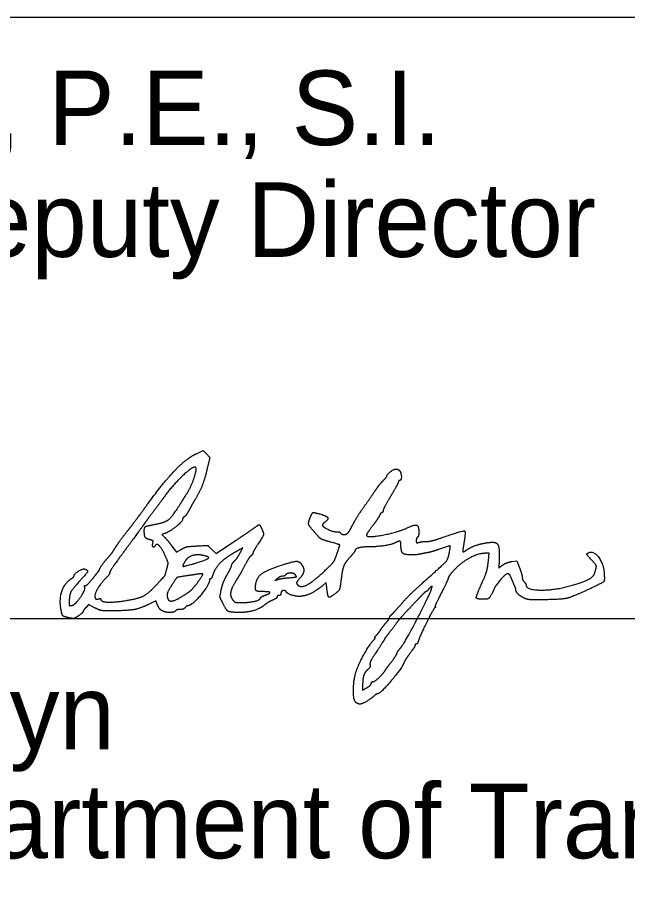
# Model space of a CAD drawing. Extents: x 0 to 39.4, y 0 to 22.
# Drawn here: x 25.677 to 26.824, y 7.305 to 8.926 of the extents above; entities that cross this region are included whole.
import ezdxf

# ---------------------------------------------------------------- set-up
doc = ezdxf.new("R2010")
doc.units = 0
for name, color, linetype in [('PV_P_Bikeway', 7, 'Continuous'), ('SH_Data', 7, 'Continuous'), ('SH_Text', 7, 'Continuous')]:
    doc.layers.add(name, color=color, linetype=linetype)

msp = doc.modelspace()

# ---------------------------------------------------------------- linework, layer by layer
at = {"layer": 'PV_P_Bikeway'}
for points in [[(26.0135, 8.1066), (26.0261, 8.1124), (26.0325, 8.1061), (26.0388, 8.0997), (26.0344, 8.081)], [(25.9536, 7.9566), (25.9486, 7.955), (25.9537, 7.9499)], [(25.9674, 7.9332), (25.9759, 7.9217), (25.9847, 7.9269)], [(26.0425, 7.9269), (26.0507, 7.9193), (26.0869, 7.9434)], [(26.0964, 7.9216), (26.1009, 7.9296), (26.0954, 7.9266)], [(26.5623, 7.9057), (26.5638, 7.9195), (26.5559, 7.9195)], [(26.6061, 7.9041), (26.6158, 7.9056), (26.6209, 7.8921)], [(26.2582, 7.8579), (26.2575, 7.8648), (26.2516, 7.8596)], [(25.8219, 7.8173), (25.8104, 7.8231), (25.8054, 7.8173)], [(25.9406, 7.8223), (25.9372, 7.8304), (25.9234, 7.8235)], [(26.3259, 7.6718), (26.3259, 7.6624), (26.3335, 7.6668)]]:
    msp.add_lwpolyline(points, dxfattribs=at)
for points in [[(25.9239, 8.0147), (25.9536, 8.0553), (25.9954, 8.0982), (26.0135, 8.1066)], [(26.012, 8.0808), (26.0084, 8.0844), (25.9698, 8.0487), (25.9545, 8.0274)], [(25.9937, 8.0287), (26.0032, 8.0436), (26.0151, 8.0777), (26.012, 8.0808)], [(26.0344, 8.081), (26.0294, 8.0598), (26.0203, 8.0362), (26.0108, 8.0203)], [(26.3715, 8.0646), (26.3715, 8.0675), (26.3847, 8.0778), (26.3884, 8.0778)], [(26.3884, 8.0778), (26.3905, 8.0779), (26.3935, 8.0766), (26.395, 8.075)], [(26.3649, 8.0565), (26.3686, 8.0602), (26.3715, 8.0638), (26.3715, 8.0646)], [(26.395, 8.075), (26.3985, 8.0716), (26.3989, 8.0563), (26.3955, 8.0563)], [(26.3511, 8.0393), (26.3551, 8.0452), (26.3613, 8.0529), (26.3649, 8.0565)], [(26.3931, 8.0538), (26.3931, 8.0524), (26.3866, 8.0403), (26.3787, 8.0269)], [(26.3955, 8.0563), (26.3942, 8.0563), (26.3931, 8.0552), (26.3931, 8.0538)], [(25.9545, 8.0274), (25.9509, 8.0224), (25.9414, 8.0098), (25.9335, 7.9993)], [(25.9832, 8.012), (25.9865, 8.0172), (25.9912, 8.0248), (25.9937, 8.0287)], [(26.3295, 8.0083), (26.3375, 8.0195), (26.3472, 8.0335), (26.3511, 8.0393)], [(25.8838, 7.9612), (25.8927, 7.9726), (25.9107, 7.9966), (25.9239, 8.0147)], [(25.9334, 7.9734), (25.954, 7.9771), (25.9681, 7.988), (25.9832, 8.012)], [(26.0108, 8.0203), (26.0073, 8.0144), (26.0021, 8.0052), (25.9993, 7.9999)], [(26.3787, 8.0269), (26.3708, 8.0135), (26.3643, 8.0012), (26.3643, 7.9994)], [(25.9335, 7.9993), (25.9256, 7.9888), (25.9175, 7.9778), (25.9155, 7.9748)], [(25.9993, 7.9999), (25.9964, 7.9946), (25.9926, 7.9894), (25.9908, 7.9884)], [(26.2275, 7.9866), (26.2312, 7.9956), (26.2343, 7.9966), (26.2471, 7.9929)], [(26.3081, 7.9747), (26.312, 7.982), (26.3216, 7.9971), (26.3295, 8.0083)], [(26.3623, 7.9963), (26.3612, 7.9963), (26.3589, 7.9933), (26.3571, 7.9897)], [(26.3643, 7.9994), (26.3643, 7.9977), (26.3634, 7.9963), (26.3623, 7.9963)], [(25.9875, 7.983), (25.9875, 7.9792), (25.9618, 7.9592), (25.9536, 7.9566)], [(25.9908, 7.9884), (25.989, 7.9873), (25.9875, 7.9849), (25.9875, 7.983)], [(26.2373, 7.9571), (26.2257, 7.9702), (26.2235, 7.977), (26.2275, 7.9866)], [(26.2471, 7.9929), (26.259, 7.9893), (26.2619, 7.9831), (26.2542, 7.9773)], [(26.3571, 7.9897), (26.3553, 7.9861), (26.3492, 7.977), (26.3435, 7.9695)], [(25.9155, 7.9748), (25.9135, 7.9719), (25.8982, 7.9509), (25.8814, 7.9283)], [(25.9155, 7.9613), (25.9155, 7.9681), (25.9196, 7.9709), (25.9334, 7.9734)], [(26.0869, 7.9434), (26.1068, 7.9566), (26.1244, 7.9686), (26.126, 7.9699)], [(26.126, 7.9699), (26.1306, 7.9737), (26.1329, 7.9728), (26.1359, 7.9662)], [(26.1359, 7.9662), (26.1403, 7.9566), (26.1394, 7.9525), (26.1291, 7.9366)], [(26.2542, 7.9773), (26.2515, 7.9752), (26.25, 7.9724), (26.251, 7.971)], [(26.251, 7.971), (26.2537, 7.9673), (26.2736, 7.9591), (26.2782, 7.9598)], [(26.2989, 7.9585), (26.3002, 7.9602), (26.3043, 7.9675), (26.3081, 7.9747)], [(26.3435, 7.9695), (26.3378, 7.962), (26.3331, 7.9548), (26.3331, 7.9534)], [(26.3331, 7.9534), (26.3331, 7.9482), (26.3927, 7.9591), (26.4107, 7.9677)], [(26.4107, 7.9677), (26.4237, 7.9739), (26.4315, 7.9707), (26.4315, 7.9593)], [(25.8622, 7.9319), (25.8652, 7.9367), (25.8749, 7.9499), (25.8838, 7.9612)], [(25.9265, 7.9449), (25.9193, 7.9467), (25.9155, 7.9524), (25.9155, 7.9613)], [(25.9537, 7.9499), (25.9565, 7.947), (25.9627, 7.9395), (25.9674, 7.9332)], [(26.2607, 7.942), (26.25, 7.9451), (26.245, 7.9483), (26.2373, 7.9571)], [(26.2782, 7.9598), (26.2804, 7.9602), (26.283, 7.9594), (26.2839, 7.958)], [(26.2839, 7.958), (26.286, 7.9545), (26.296, 7.9549), (26.2989, 7.9585)], [(26.4291, 7.9495), (26.4278, 7.9487), (26.4267, 7.9459), (26.4267, 7.9432)], [(26.4315, 7.9593), (26.4315, 7.9547), (26.4304, 7.9503), (26.4291, 7.9495)], [(26.4451, 7.9416), (26.4492, 7.9414), (26.4622, 7.9446), (26.4739, 7.9486)], [(26.4739, 7.9486), (26.5142, 7.9625), (26.5202, 7.9608), (26.516, 7.937)], [(25.8459, 7.91), (25.8525, 7.9173), (25.8568, 7.923), (25.8622, 7.9319)], [(25.9316, 7.9386), (25.9325, 7.9422), (25.9313, 7.9437), (25.9265, 7.9449)], [(25.9359, 7.9338), (25.9335, 7.9299), (25.9303, 7.9335), (25.9316, 7.9386)], [(25.9547, 7.9152), (25.9486, 7.9289), (25.9388, 7.9386), (25.9359, 7.9338)], [(25.9847, 7.9269), (25.9912, 7.9308), (25.9988, 7.9324), (26.0139, 7.9333)], [(26.0139, 7.9333), (26.0343, 7.9345), (26.0344, 7.9345), (26.0425, 7.9269)], [(26.1291, 7.9366), (26.1238, 7.9284), (26.1195, 7.9208), (26.1195, 7.9197)], [(26.2775, 7.9182), (26.2832, 7.9351), (26.2828, 7.9356), (26.2607, 7.942)], [(26.3358, 7.9315), (26.3243, 7.9315), (26.3115, 7.9277), (26.3115, 7.9243)], [(26.3865, 7.9389), (26.3809, 7.9359), (26.3507, 7.9315), (26.3358, 7.9315)], [(26.3979, 7.9342), (26.3979, 7.9415), (26.3942, 7.943), (26.3865, 7.9389)], [(26.4172, 7.9165), (26.4048, 7.9166), (26.3979, 7.9229), (26.3979, 7.9342)], [(26.4267, 7.9432), (26.4267, 7.9393), (26.4277, 7.9387), (26.4321, 7.9401)], [(26.4321, 7.9401), (26.4351, 7.9411), (26.4409, 7.9417), (26.4451, 7.9416)], [(26.4891, 7.922), (26.4912, 7.9335), (26.4895, 7.9339), (26.4685, 7.9266)], [(26.516, 7.937), (26.5147, 7.9293), (26.514, 7.9227), (26.5144, 7.9222)], [(26.522, 7.9261), (26.5292, 7.9312), (26.5475, 7.9375), (26.5611, 7.9396)], [(26.5611, 7.9396), (26.5758, 7.9419), (26.5834, 7.9315), (26.5826, 7.9103)], [(25.8814, 7.9283), (25.8646, 7.9056), (25.8508, 7.8855), (25.8507, 7.8835)], [(25.958, 7.8907), (25.9606, 7.9005), (25.9603, 7.9027), (25.9547, 7.9152)], [(26.0257, 7.9156), (26.0149, 7.9178), (25.9975, 7.9127), (25.9932, 7.9061)], [(26.0151, 7.9021), (26.0344, 7.908), (26.0383, 7.9131), (26.0257, 7.9156)], [(26.0954, 7.9266), (26.072, 7.9141), (26.0492, 7.8934), (26.0451, 7.8809)], [(26.0836, 7.9035), (26.0891, 7.9095), (26.0916, 7.913), (26.0964, 7.9216)], [(26.116, 7.9148), (26.114, 7.9131), (26.1109, 7.9089), (26.1091, 7.9055)], [(26.1195, 7.9197), (26.1195, 7.9186), (26.1179, 7.9164), (26.116, 7.9148)], [(26.2592, 7.8909), (26.2696, 7.901), (26.2738, 7.9071), (26.2775, 7.9182)], [(26.3115, 7.9243), (26.3115, 7.9234), (26.3073, 7.918), (26.3022, 7.9123)], [(26.4339, 7.9179), (26.4306, 7.9172), (26.4231, 7.9165), (26.4172, 7.9165)], [(26.4471, 7.9205), (26.4432, 7.9199), (26.4372, 7.9187), (26.4339, 7.9179)], [(26.4443, 7.869), (26.4798, 7.9006), (26.4867, 7.9087), (26.4891, 7.922)], [(26.4685, 7.9266), (26.4607, 7.9239), (26.4511, 7.9212), (26.4471, 7.9205)], [(26.5559, 7.9195), (26.5433, 7.9195), (26.5095, 7.9011), (26.4973, 7.8875)], [(26.5144, 7.9222), (26.5149, 7.9218), (26.5183, 7.9235), (26.522, 7.9261)], [(26.7527, 7.9109), (26.7474, 7.9166), (26.7472, 7.9192), (26.7518, 7.921)], [(26.7518, 7.921), (26.7604, 7.9243), (26.7788, 7.8994), (26.7798, 7.8831)], [(25.8315, 7.8895), (25.8315, 7.8911), (25.8407, 7.9041), (25.8459, 7.91)], [(25.9932, 7.9061), (25.9861, 7.8954), (25.9907, 7.8945), (26.0151, 7.9021)], [(26.0796, 7.8965), (26.0799, 7.8982), (26.0817, 7.9014), (26.0836, 7.9035)], [(26.1091, 7.9055), (26.101, 7.89), (26.0932, 7.8763), (26.087, 7.8666)], [(26.1629, 7.8938), (26.1947, 7.9044), (26.2082, 7.9048), (26.2132, 7.8953)], [(26.3022, 7.9123), (26.2937, 7.9028), (26.288, 7.8903), (26.2864, 7.8775)], [(26.5476, 7.8579), (26.5566, 7.8778), (26.5607, 7.8909), (26.5623, 7.9057)], [(26.5826, 7.9103), (26.582, 7.8919), (26.5818, 7.8921), (26.5896, 7.8977)], [(26.5896, 7.8977), (26.5933, 7.9003), (26.6008, 7.9032), (26.6061, 7.9041)], [(26.7618, 7.8818), (26.7658, 7.8936), (26.7643, 7.8985), (26.7527, 7.9109)], [(25.7836, 7.8775), (25.7836, 7.8812), (25.8004, 7.8912), (25.8041, 7.8898)], [(25.8041, 7.8898), (25.8101, 7.8875), (25.8078, 7.8826), (25.7935, 7.8667)], [(25.817, 7.8703), (25.8224, 7.8769), (25.8278, 7.8836), (25.8291, 7.8852)], [(25.8291, 7.8852), (25.8304, 7.8868), (25.8315, 7.8887), (25.8315, 7.8895)], [(25.8507, 7.8835), (25.8506, 7.8815), (25.8473, 7.8767), (25.8433, 7.8728)], [(25.9383, 7.8602), (25.9544, 7.8778), (25.9547, 7.8783), (25.958, 7.8907)], [(26.0712, 7.8794), (26.0756, 7.887), (26.0794, 7.8947), (26.0796, 7.8965)], [(26.1253, 7.8627), (26.1274, 7.874), (26.1436, 7.8873), (26.1629, 7.8938)], [(26.199, 7.8795), (26.1962, 7.8829), (26.1828, 7.8821), (26.1806, 7.8784)], [(26.2022, 7.8621), (26.2076, 7.8534), (26.2343, 7.8669), (26.2592, 7.8909)], [(26.2132, 7.8953), (26.2165, 7.8893), (26.213, 7.8779), (26.2056, 7.87)], [(26.4973, 7.8875), (26.4915, 7.8811), (26.4867, 7.8745), (26.4867, 7.8729)], [(26.6209, 7.8921), (26.6236, 7.8846), (26.6259, 7.8765), (26.6259, 7.874)], [(26.713, 7.8575), (26.7366, 7.8637), (26.7596, 7.8751), (26.7618, 7.8818)], [(26.7798, 7.8831), (26.7808, 7.8678), (26.7781, 7.8646), (26.7547, 7.8537)], [(25.7587, 7.8159), (25.7557, 7.8344), (25.7665, 7.8644), (25.7789, 7.8722)], [(25.7935, 7.8667), (25.7798, 7.8515), (25.7748, 7.8414), (25.7742, 7.8275)], [(25.7789, 7.8722), (25.7814, 7.8738), (25.7835, 7.8762), (25.7836, 7.8775)], [(25.8047, 7.859), (25.8061, 7.8586), (25.8117, 7.8637), (25.817, 7.8703)], [(25.8433, 7.8728), (25.8335, 7.8631), (25.8211, 7.841), (25.8229, 7.8364)], [(25.9959, 7.8773), (25.9782, 7.8747), (25.9761, 7.8736), (25.9688, 7.8623)], [(25.9884, 7.8396), (25.9996, 7.8466), (26.0106, 7.8571), (26.0183, 7.8683)], [(26.0133, 7.8799), (26.0077, 7.879), (25.9999, 7.8779), (25.9959, 7.8773)], [(26.0379, 7.8685), (26.0378, 7.86), (26.0047, 7.8211), (25.9975, 7.8211)], [(26.0183, 7.8683), (26.0261, 7.8796), (26.0252, 7.8818), (26.0133, 7.8799)], [(26.0399, 7.8715), (26.0388, 7.8715), (26.0379, 7.8702), (26.0379, 7.8685)], [(26.0451, 7.8809), (26.0434, 7.8758), (26.041, 7.8715), (26.0399, 7.8715)], [(26.0603, 7.8515), (26.0619, 7.8592), (26.0668, 7.8718), (26.0712, 7.8794)], [(26.087, 7.8666), (26.0791, 7.854), (26.0768, 7.8387), (26.0819, 7.8319)], [(26.1662, 7.8725), (26.1616, 7.8688), (26.1616, 7.8687), (26.1663, 7.8704)], [(26.175, 7.8763), (26.1727, 7.8763), (26.1687, 7.8746), (26.1662, 7.8725)], [(26.1663, 7.8704), (26.169, 7.8713), (26.1765, 7.8726), (26.1831, 7.8732)], [(26.1806, 7.8784), (26.1798, 7.8773), (26.1773, 7.8763), (26.175, 7.8763)], [(26.1831, 7.8732), (26.1999, 7.8747), (26.2023, 7.8757), (26.199, 7.8795)], [(26.2056, 7.87), (26.2029, 7.8671), (26.2013, 7.8635), (26.2022, 7.8621)], [(26.2864, 7.8775), (26.2835, 7.855), (26.2818, 7.8495), (26.2761, 7.8451)], [(26.4002, 7.8262), (26.4075, 7.8346), (26.4273, 7.8539), (26.4443, 7.869)], [(26.4867, 7.8729), (26.4867, 7.8714), (26.4808, 7.8585), (26.4735, 7.8444)], [(26.5991, 7.8811), (26.5948, 7.8811), (26.5766, 7.8606), (26.5719, 7.8504)], [(26.6047, 7.8745), (26.6032, 7.8781), (26.6007, 7.8811), (26.5991, 7.8811)], [(26.6107, 7.8603), (26.6089, 7.8645), (26.6062, 7.8709), (26.6047, 7.8745)], [(26.6259, 7.874), (26.6259, 7.8715), (26.6275, 7.8678), (26.6295, 7.8659)], [(26.6295, 7.8659), (26.6315, 7.8639), (26.6331, 7.8612), (26.6331, 7.8599)], [(25.7791, 7.8215), (25.7854, 7.8225), (25.8055, 7.8509), (25.8035, 7.8561)], [(25.8035, 7.8561), (25.8028, 7.8581), (25.8033, 7.8594), (25.8047, 7.859)], [(25.8818, 7.8309), (25.9045, 7.8345), (25.9242, 7.8447), (25.9383, 7.8602)], [(25.9688, 7.8623), (25.9606, 7.8497), (25.9575, 7.8399), (25.9597, 7.8341)], [(26.0623, 7.8275), (26.0578, 7.8366), (26.0576, 7.8389), (26.0603, 7.8515)], [(26.1389, 7.8475), (26.1274, 7.8475), (26.1233, 7.8521), (26.1253, 7.8627)], [(26.1818, 7.8477), (26.1798, 7.851), (26.1723, 7.8478), (26.1723, 7.8437)], [(26.2516, 7.8596), (26.2423, 7.8515), (26.2223, 7.8408), (26.2131, 7.8392)], [(26.2761, 7.8451), (26.2644, 7.8358), (26.26, 7.839), (26.2582, 7.8579)], [(26.3976, 7.7424), (26.4053, 7.7511), (26.4585, 7.8549), (26.4564, 7.857)], [(26.4507, 7.8529), (26.4483, 7.8499), (26.4457, 7.8475), (26.445, 7.8475)], [(26.4564, 7.857), (26.4557, 7.8577), (26.4531, 7.8559), (26.4507, 7.8529)], [(26.5549, 7.8331), (26.5404, 7.8331), (26.5388, 7.8385), (26.5476, 7.8579)], [(26.5719, 7.8504), (26.5661, 7.838), (26.5613, 7.8331), (26.5549, 7.8331)], [(26.614, 7.8507), (26.614, 7.8519), (26.6125, 7.8562), (26.6107, 7.8603)], [(26.6297, 7.8352), (26.6226, 7.8385), (26.6142, 7.8469), (26.614, 7.8507)], [(26.6331, 7.8599), (26.6331, 7.8513), (26.6837, 7.8498), (26.713, 7.8575)], [(26.7547, 7.8537), (26.7199, 7.8373), (26.6989, 7.8326), (26.6595, 7.8321)], [(25.8229, 7.8364), (25.8238, 7.834), (25.8262, 7.833), (25.8292, 7.8338)], [(25.8292, 7.8338), (25.8318, 7.8345), (25.8339, 7.8342), (25.8339, 7.8331)], [(25.8339, 7.8331), (25.8339, 7.8284), (25.8596, 7.8273), (25.8818, 7.8309)], [(25.9597, 7.8341), (25.9617, 7.8288), (25.9753, 7.8314), (25.9884, 7.8396)], [(26.0995, 7.8271), (26.1135, 7.8271), (26.1339, 7.8322), (26.1339, 7.8357)], [(26.1339, 7.8357), (26.1339, 7.8368), (26.1376, 7.8389), (26.1422, 7.8406)], [(26.1422, 7.8406), (26.1525, 7.8443), (26.151, 7.8475), (26.1389, 7.8475)], [(26.1597, 7.8329), (26.1524, 7.8296), (26.1448, 7.8251), (26.1405, 7.8216)], [(26.1651, 7.8379), (26.1651, 7.8365), (26.1627, 7.8343), (26.1597, 7.8329)], [(26.1687, 7.8403), (26.1667, 7.8403), (26.1651, 7.8392), (26.1651, 7.8379)], [(26.1723, 7.8437), (26.1723, 7.8418), (26.1707, 7.8403), (26.1687, 7.8403)], [(26.2131, 7.8392), (26.2045, 7.8376), (26.1847, 7.843), (26.1818, 7.8477)], [(26.4362, 7.8397), (26.4321, 7.8354), (26.4215, 7.8243), (26.4127, 7.8151)], [(26.445, 7.8475), (26.4442, 7.8475), (26.4402, 7.844), (26.4362, 7.8397)], [(26.4735, 7.8444), (26.4662, 7.8303), (26.4611, 7.8187), (26.4621, 7.8187)], [(26.6595, 7.8321), (26.6446, 7.832), (26.6343, 7.833), (26.6297, 7.8352)], [(25.7742, 7.8275), (25.774, 7.8219), (25.7748, 7.8209), (25.7791, 7.8215)], [(25.8054, 7.8173), (25.8026, 7.8141), (25.8003, 7.8107), (25.8003, 7.8097)], [(25.8527, 7.8115), (25.8371, 7.8115), (25.8312, 7.8126), (25.8219, 7.8173)], [(25.9234, 7.8235), (25.9078, 7.8158), (25.8826, 7.8115), (25.8527, 7.8115)], [(25.9488, 7.8117), (25.9461, 7.8131), (25.9424, 7.8179), (25.9406, 7.8223)], [(25.9923, 7.8175), (25.9907, 7.8155), (25.9863, 7.8139), (25.9826, 7.8139)], [(25.9975, 7.8211), (25.9963, 7.8211), (25.994, 7.8195), (25.9923, 7.8175)], [(26.094, 7.8084), (26.0765, 7.8085), (26.0695, 7.8127), (26.0623, 7.8275)], [(26.0819, 7.8319), (26.0848, 7.8281), (26.0883, 7.8271), (26.0995, 7.8271)], [(26.1405, 7.8216), (26.1328, 7.8152), (26.1085, 7.8083), (26.094, 7.8084)], [(26.3818, 7.8058), (26.3847, 7.8087), (26.393, 7.8179), (26.4002, 7.8262)], [(26.4613, 7.8169), (26.4587, 7.815), (26.4334, 7.764), (26.4305, 7.7545)], [(26.4621, 7.8187), (26.4631, 7.8187), (26.4628, 7.8178), (26.4613, 7.8169)], [(25.7752, 7.7981), (25.7644, 7.8002), (25.7605, 7.8043), (25.7587, 7.8159)], [(25.792, 7.8022), (25.7854, 7.7978), (25.7818, 7.7969), (25.7752, 7.7981)], [(25.8003, 7.8097), (25.8003, 7.8087), (25.7965, 7.8054), (25.792, 7.8022)], [(25.9743, 7.8115), (25.9723, 7.8083), (25.9549, 7.8084), (25.9488, 7.8117)], [(25.9826, 7.8139), (25.9789, 7.8139), (25.9751, 7.8128), (25.9743, 7.8115)], [(26.3764, 7.7986), (26.3764, 7.7998), (26.3788, 7.803), (26.3818, 7.8058)], [(26.4127, 7.8151), (26.4039, 7.8058), (26.394, 7.7946), (26.3907, 7.7901)], [(26.3595, 7.7755), (26.3615, 7.7786), (26.3661, 7.7846), (26.3697, 7.7888)], [(26.3907, 7.7901), (26.3826, 7.7792), (26.3721, 7.7654), (26.3692, 7.7618)], [(26.3697, 7.7888), (26.3734, 7.7931), (26.3763, 7.7975), (26.3764, 7.7986)], [(26.3517, 7.7655), (26.354, 7.7679), (26.3575, 7.7724), (26.3595, 7.7755)], [(26.3157, 7.7031), (26.3216, 7.7179), (26.3388, 7.7478), (26.3459, 7.7557)], [(26.3459, 7.7557), (26.3486, 7.7587), (26.35, 7.7611), (26.3491, 7.7611)], [(26.3491, 7.7611), (26.3483, 7.7611), (26.3494, 7.7631), (26.3517, 7.7655)], [(26.3667, 7.7579), (26.3667, 7.7574), (26.3604, 7.7474), (26.3527, 7.7358)], [(26.3692, 7.7618), (26.3678, 7.7602), (26.3667, 7.7585), (26.3667, 7.7579)], [(26.4305, 7.7545), (26.4296, 7.7515), (26.4278, 7.7491), (26.4266, 7.7491)], [(26.3527, 7.7358), (26.344, 7.7228), (26.339, 7.713), (26.3397, 7.7103)], [(26.3907, 7.7321), (26.3907, 7.7335), (26.3938, 7.7381), (26.3976, 7.7424)], [(26.4243, 7.7466), (26.4243, 7.7452), (26.4201, 7.7385), (26.4148, 7.7316)], [(26.4266, 7.7491), (26.4253, 7.7491), (26.4243, 7.748), (26.4243, 7.7466)], [(26.3805, 7.7163), (26.3861, 7.7237), (26.3907, 7.7308), (26.3907, 7.7321)], [(26.4148, 7.7316), (26.4096, 7.7247), (26.4045, 7.7167), (26.4034, 7.7138)], [(26.3139, 7.6387), (26.308, 7.6424), (26.3092, 7.6867), (26.3157, 7.7031)], [(26.3397, 7.7103), (26.3404, 7.7078), (26.3388, 7.7041), (26.3361, 7.7017)], [(26.4034, 7.7138), (26.3998, 7.704), (26.3586, 7.6555), (26.3539, 7.6555)], [(26.3679, 7.699), (26.3692, 7.7012), (26.3749, 7.7089), (26.3805, 7.7163)], [(26.3361, 7.7017), (26.3301, 7.6965), (26.3259, 7.6842), (26.3259, 7.6718)], [(26.3451, 7.6783), (26.347, 7.6771), (26.3637, 7.6923), (26.3679, 7.699)], [(26.3335, 7.6668), (26.3376, 7.6692), (26.3415, 7.673), (26.3421, 7.6753)], [(26.3421, 7.6753), (26.3428, 7.6776), (26.3441, 7.6789), (26.3451, 7.6783)], [(26.3539, 7.6555), (26.3526, 7.6555), (26.3492, 7.6535), (26.3465, 7.6509)], [(26.3205, 7.6363), (26.3188, 7.6364), (26.3159, 7.6374), (26.3139, 7.6387)], [(26.3465, 7.6509), (26.3403, 7.6452), (26.3243, 7.6363), (26.3205, 7.6363)]]:
    msp.add_open_spline(points, degree=2, dxfattribs=at)
at = {"layer": 'SH_Data'}
for p, q in [((24.5279, 8.9262), (28.0279, 8.9262)), ((24.5279, 7.7968), (28.0279, 7.7968))]:
    msp.add_line(p, q, dxfattribs=at)

# ---------------------------------------------------------------- texts
at = {"layer": 'SH_Text'}
for s, p in [('Pat McColley, P.E., S.I.', (24.5279, 8.6862)), ('District       Deputy Director', (24.5279, 8.4762)), ('Pamela Boratyn', (24.5282, 7.5514)), ('Director, Department of Transportation', (24.5279, 7.3468))]:
    msp.add_text(s, height=0.14, dxfattribs=at).set_placement(p)

doc.saveas('drawing.dxf')
